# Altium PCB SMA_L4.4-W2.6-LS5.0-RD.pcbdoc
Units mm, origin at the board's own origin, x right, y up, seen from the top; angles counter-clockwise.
Board outline 18.9 x 15.65 mm, 2 copper layers (Top Layer, Bottom Layer), stack 0.07 mm thick; 1 components, 0 nets, 2 pads, 0 vias.
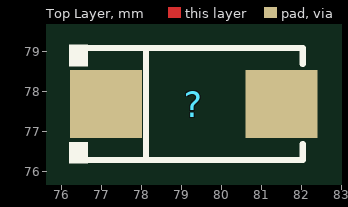
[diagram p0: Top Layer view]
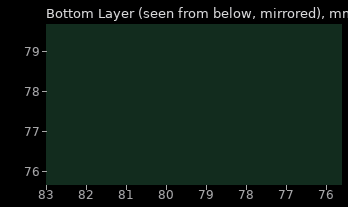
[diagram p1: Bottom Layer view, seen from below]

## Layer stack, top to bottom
Top Solder Mask Layer: solder mask 0.01, Dk 3.3
Top Layer: signal copper 0.035
Bottom Layer: signal copper 0.035
Bottom Solder Mask Layer: solder mask 0.01, Dk 3.3

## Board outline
88.75,69.85 69.85,69.85 69.85,85.505 88.75,85.505

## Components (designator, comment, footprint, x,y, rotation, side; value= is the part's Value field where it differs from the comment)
? "SMA_L4.4-W2.6-LS5.0-RD" SMA_L4.4-W2.6-LS5.0-RD 79.307,77.677 r0 top

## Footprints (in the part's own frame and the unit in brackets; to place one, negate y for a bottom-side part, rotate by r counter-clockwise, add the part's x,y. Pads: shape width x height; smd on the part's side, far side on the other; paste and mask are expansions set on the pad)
SMA_L4.4-W2.6-LS5.0-RD [mm]
  rect 1.8x1.7 smd paste+0 mask+0.051: 1(-2.192,0) 2(2.192,0)
  silkscreen extent -3.11,-1.48 2.73,1.48

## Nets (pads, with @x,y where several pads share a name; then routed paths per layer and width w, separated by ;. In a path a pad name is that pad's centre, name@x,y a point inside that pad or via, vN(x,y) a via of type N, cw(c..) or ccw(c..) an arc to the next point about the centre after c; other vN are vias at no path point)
pads on no net: ?.1 ?.2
